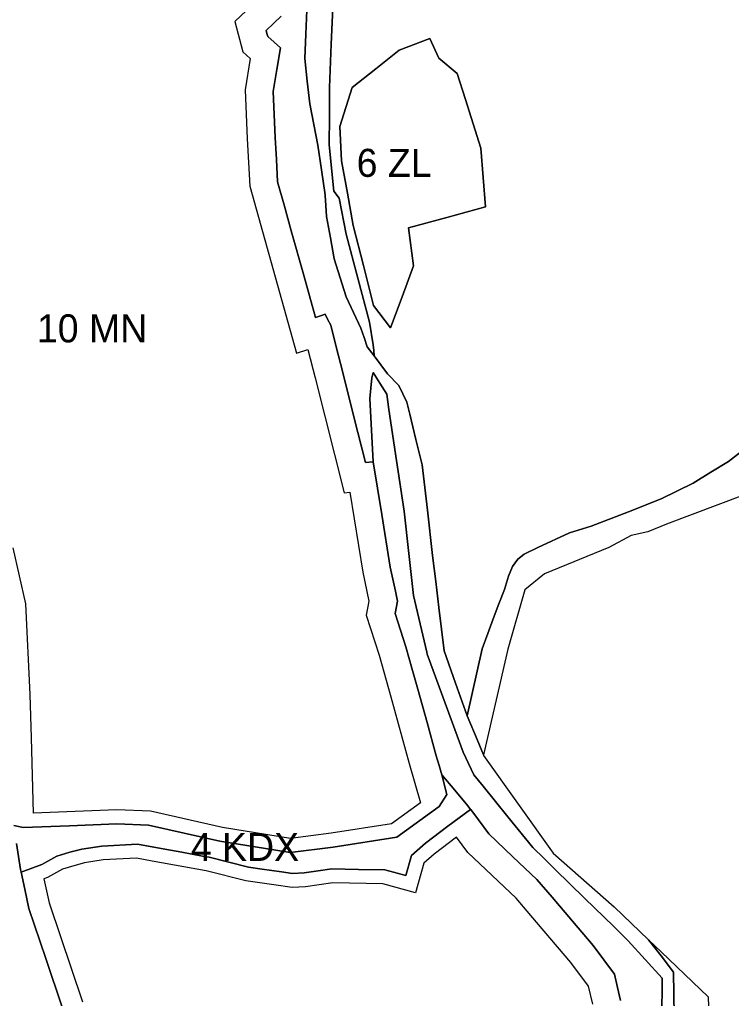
# Model space of a CAD drawing. Extents: x 7423691 to 7425475, y 5552085 to 5554331.
# Drawn here: x 7424586.6 to 7424789.8, y 5552384.7 to 5552663.9 of the extents above; entities that cross this region are included whole.
import ezdxf

# ---------------------------------------------------------------- set-up
doc = ezdxf.new("R2010")
doc.units = 0
for name, color, linetype in [('linia_zabudowy_nieprzekraczalna', 7, 'Continuous'), ('linie_rozgraniczajace', 7, 'Continuous'), ('oznaczenia_przeznaczen', 7, 'Continuous')]:
    doc.layers.add(name, color=color, linetype=linetype)

msp = doc.modelspace()

# ---------------------------------------------------------------- linework, layer by layer
at = {"layer": 'linia_zabudowy_nieprzekraczalna'}
for points in [[(7424652.99, 5552668.07), (7424648.05, 5552663.36), (7424650.33, 5552654.77), (7424652.45, 5552652.88), (7424650.97, 5552643.95), (7424651.59, 5552629.88), (7424652.3, 5552616.38), (7424665.67, 5552568.76), (7424668.93, 5552569.83), (7424671.01, 5552561.69), (7424679.28, 5552528.94), (7424680.84, 5552529.09), (7424684.57, 5552506.25), (7424686.32, 5552498.02), (7424685.51, 5552494.03), (7424689.21, 5552482.64), (7424692.6, 5552470.77), (7424697.85, 5552451.69), (7424701.04, 5552440.51), (7424692.72, 5552434.49), (7424675.54, 5552431.79), (7424663.95, 5552430.31), (7424644.53, 5552433.48), (7424623.94, 5552438.1), (7424614.37, 5552438.45), (7424590.57, 5552437.52), (7424590, 5552459.04), (7424589.67, 5552471.43), (7424588.36, 5552497.25), (7424584.74, 5552513.23)], [(7424750.2, 5552383.01), (7424748.98, 5552388.13), (7424743.98, 5552394.96), (7424732.52, 5552408.34), (7424728.3, 5552413.26), (7424714.57, 5552426.28), (7424711.31, 5552430.64), (7424704.96, 5552425.88), (7424701.98, 5552423.27), (7424699.66, 5552414.8), (7424690.27, 5552417.38), (7424676.02, 5552417.62), (7424668.26, 5552416.52), (7424664.37, 5552416.29), (7424659.2, 5552417.06), (7424651.17, 5552418.22), (7424639.85, 5552421.06), (7424624.43, 5552423.87), (7424620.02, 5552424.68), (7424610.48, 5552424.18), (7424605.15, 5552423.32), (7424602.08, 5552422.55), (7424598.84, 5552421.55), (7424594.6, 5552419.21), (7424593.57, 5552418.83), (7424595.08, 5552411.93), (7424604.56, 5552383.75)]]:
    msp.add_lwpolyline(points, dxfattribs=at)
at = {"layer": 'linie_rozgraniczajace'}
for points in [[(7424676.09, 5552669.35), (7424675.59, 5552656.96), (7424675.09, 5552644.56), (7424675.05, 5552636.4), (7424675, 5552628.25), (7424676.3, 5552615.01), (7424677.81, 5552613), (7424679.87, 5552602.69), (7424683.17, 5552590.17), (7424686.46, 5552577.65), (7424687.57, 5552571.15), (7424687.68, 5552569.56), (7424687.79, 5552567.97), (7424685.8, 5552570.62), (7424684.92, 5552573.25), (7424684.03, 5552575.88), (7424681.92, 5552580.34), (7424679.8, 5552584.8), (7424678.12, 5552590.26), (7424676.43, 5552595.72), (7424675.33, 5552601.72), (7424674.23, 5552607.73), (7424674.03, 5552610.86), (7424673.85, 5552613.72), (7424673.83, 5552613.99), (7424672.8, 5552621.07), (7424671.77, 5552628.15), (7424670.61, 5552634.05), (7424669.45, 5552639.95), (7424668.74, 5552646.42), (7424668.02, 5552652.88), (7424668.3, 5552659.76), (7424668.57, 5552666.64)], [(7424694.82, 5552559.59), (7424691.65, 5552562.83), (7424689.72, 5552565.4), (7424687.79, 5552567.97), (7424687.68, 5552569.56), (7424687.57, 5552571.15), (7424686.46, 5552577.65), (7424683.17, 5552590.17), (7424679.87, 5552602.69), (7424677.81, 5552613), (7424676.3, 5552615.01), (7424675, 5552628.25), (7424675.05, 5552636.4), (7424675.09, 5552644.56), (7424675.59, 5552656.96), (7424676.09, 5552669.35)], [(7424668.57, 5552666.64), (7424668.3, 5552659.76), (7424668.02, 5552652.88), (7424668.74, 5552646.42), (7424669.45, 5552639.95), (7424670.61, 5552634.05), (7424671.77, 5552628.15), (7424672.8, 5552621.07), (7424673.83, 5552613.99), (7424673.85, 5552613.72), (7424674.03, 5552610.86), (7424674.23, 5552607.73), (7424675.33, 5552601.72), (7424676.43, 5552595.72), (7424678.12, 5552590.26), (7424679.8, 5552584.8), (7424681.92, 5552580.34), (7424684.03, 5552575.88), (7424684.92, 5552573.25), (7424685.8, 5552570.62), (7424687.79, 5552567.97), (7424689.72, 5552565.4), (7424691.65, 5552562.83), (7424694.82, 5552559.59), (7424695.99, 5552557.18), (7424697.15, 5552554.78), (7424697.98, 5552551.37), (7424699.74, 5552544.14), (7424701.51, 5552536.91), (7424703.01, 5552523.99), (7424704.51, 5552511.07), (7424705.39, 5552503.65), (7424706.28, 5552496.22), (7424707.01, 5552490.04), (7424707.75, 5552483.85), (7424711.07, 5552474.59), (7424714.39, 5552465.34), (7424715.15, 5552463.48), (7424716.71, 5552459.73), (7424719.02, 5552454.16), (7424718.98, 5552453.98), (7424738.87, 5552426.09), (7424756.36, 5552410.77), (7424766.12, 5552401.43), (7424769.7, 5552396.82), (7424773.28, 5552392.2), (7424773.42, 5552379.79)], [(7424661.29, 5552664.94), (7424659.14, 5552662.89), (7424657, 5552660.84), (7424657.22, 5552659.99), (7424657.45, 5552659.15), (7424659.26, 5552657.53), (7424661.07, 5552655.92), (7424660.03, 5552649.7), (7424658.99, 5552643.47), (7424659.29, 5552636.87), (7424659.58, 5552630.27), (7424659.91, 5552623.98), (7424660.24, 5552617.69), (7424662.2, 5552610.71), (7424664.16, 5552603.72), (7424667.63, 5552591.35), (7424671.11, 5552578.97), (7424672.46, 5552579.42), (7424673.81, 5552579.86), (7424674.62, 5552578.31), (7424675.42, 5552576.76), (7424677.09, 5552570.21), (7424678.76, 5552563.66), (7424682.06, 5552550.61), (7424685.36, 5552537.56), (7424687.52, 5552537.76), (7424689.98, 5552522.75), (7424692.43, 5552507.73), (7424693.89, 5552500.9), (7424694.5, 5552498.06), (7424693.77, 5552494.49), (7424695.31, 5552489.73), (7424696.86, 5552484.97), (7424698.58, 5552478.95), (7424700.3, 5552472.93), (7424702.93, 5552463.39), (7424705.56, 5552453.85), (7424706.33, 5552451.14), (7424707.1, 5552448.44), (7424708.59, 5552442.85), (7424706.37, 5552439.43), (7424694.29, 5552430.69), (7424676.1, 5552427.83), (7424663.88, 5552426.27), (7424653.83, 5552427.91), (7424643.77, 5552429.55), (7424633.6, 5552431.84), (7424623.42, 5552434.12), (7424614.37, 5552434.45), (7424600.87, 5552433.92), (7424587.67, 5552433.41), (7424584.95, 5552434.02)], [(7424689.47, 5552560.17), (7424687.53, 5552563.24), (7424687.14, 5552561.78), (7424686.85, 5552558.79), (7424686.57, 5552555.8), (7424687.04, 5552546.78), (7424687.52, 5552537.76), (7424685.36, 5552537.56), (7424682.06, 5552550.61), (7424678.76, 5552563.66), (7424677.09, 5552570.21), (7424675.42, 5552576.76), (7424674.62, 5552578.31), (7424673.81, 5552579.86), (7424672.46, 5552579.42), (7424671.11, 5552578.97), (7424667.63, 5552591.35), (7424664.16, 5552603.72), (7424662.2, 5552610.71), (7424660.24, 5552617.69), (7424659.91, 5552623.98), (7424659.58, 5552630.27), (7424659.29, 5552636.87), (7424658.99, 5552643.47), (7424660.03, 5552649.7), (7424661.07, 5552655.92), (7424659.26, 5552657.53), (7424657.45, 5552659.15), (7424657.22, 5552659.99), (7424657, 5552660.84), (7424659.14, 5552662.89), (7424661.29, 5552664.94)], [(7424686.57, 5552555.8), (7424686.85, 5552558.79), (7424687.14, 5552561.78), (7424687.53, 5552563.24), (7424689.47, 5552560.17), (7424691.41, 5552557.1), (7424692.05, 5552552.73), (7424694.2, 5552538.19), (7424696.35, 5552523.65), (7424697.72, 5552511.64), (7424699.09, 5552499.62), (7424700.98, 5552491.53), (7424702.87, 5552483.44), (7424702.99, 5552482.86), (7424708.09, 5552468.9), (7424713.19, 5552454.95), (7424714.74, 5552451.72), (7424716.29, 5552448.48), (7424717.6, 5552446.86), (7424718.91, 5552445.24), (7424726, 5552436.5), (7424733.09, 5552427.75), (7424736.3, 5552424.59), (7424739.51, 5552421.43), (7424747.87, 5552413.32), (7424756.24, 5552405.22), (7424760.31, 5552401.09), (7424765.15, 5552395.77), (7424769.99, 5552390.45), (7424769.9, 5552378.7)], [(7424769.9, 5552378.7), (7424769.99, 5552390.45), (7424765.15, 5552395.77), (7424760.31, 5552401.09), (7424756.24, 5552405.22), (7424747.87, 5552413.32), (7424739.51, 5552421.43), (7424736.3, 5552424.59), (7424733.09, 5552427.75), (7424726, 5552436.5), (7424718.91, 5552445.24), (7424717.6, 5552446.86), (7424716.29, 5552448.48), (7424714.74, 5552451.72), (7424713.19, 5552454.95), (7424708.09, 5552468.9), (7424702.99, 5552482.86), (7424702.87, 5552483.44), (7424700.98, 5552491.53), (7424699.09, 5552499.62), (7424697.72, 5552511.64), (7424696.35, 5552523.65), (7424694.2, 5552538.19), (7424692.05, 5552552.73), (7424691.41, 5552557.1), (7424689.47, 5552560.17)], [(7424797.91, 5552544.77), (7424788.94, 5552537.9), (7424783.92, 5552534.8), (7424778.91, 5552531.69), (7424769.74, 5552527.22), (7424760.37, 5552523.55), (7424749.73, 5552519.37), (7424743.59, 5552517.52), (7424734.54, 5552513.36), (7424730.64, 5552511.46), (7424728.78, 5552510.02), (7424727.29, 5552507.92), (7424726.2, 5552505.18), (7424725.02, 5552501.39), (7424723.43, 5552497.22), (7424721.82, 5552492.98), (7424720.26, 5552488.76), (7424718.65, 5552484.42), (7424714.39, 5552465.34), (7424711.07, 5552474.59), (7424707.75, 5552483.85), (7424707.01, 5552490.04), (7424706.28, 5552496.22), (7424705.39, 5552503.65), (7424704.51, 5552511.07), (7424703.01, 5552523.99), (7424701.51, 5552536.91), (7424699.74, 5552544.14), (7424697.98, 5552551.37), (7424697.15, 5552554.78), (7424695.99, 5552557.18), (7424694.82, 5552559.59)], [(7424758.16, 5552384.1), (7424757.28, 5552387.83), (7424756.39, 5552391.56), (7424753.37, 5552395.68), (7424750.34, 5552399.81), (7424744.47, 5552406.68), (7424738.6, 5552413.54), (7424734.24, 5552418.63), (7424727.4, 5552425.12), (7424720.57, 5552431.62), (7424717.56, 5552435.65), (7424715.38, 5552438.55), (7424715.36, 5552438.59), (7424714.54, 5552439.67), (7424710.82, 5552444.06), (7424707.1, 5552448.44), (7424706.33, 5552451.14), (7424705.56, 5552453.85), (7424702.93, 5552463.39), (7424700.3, 5552472.93), (7424698.58, 5552478.95), (7424696.86, 5552484.97), (7424695.31, 5552489.73), (7424693.77, 5552494.49), (7424694.5, 5552498.06), (7424693.89, 5552500.9), (7424692.43, 5552507.73), (7424689.98, 5552522.75), (7424687.52, 5552537.76), (7424687.04, 5552546.78), (7424686.57, 5552555.8)], [(7424714.39, 5552465.34), (7424718.65, 5552484.42), (7424720.26, 5552488.76), (7424721.82, 5552492.98), (7424723.43, 5552497.22), (7424725.02, 5552501.39), (7424726.2, 5552505.18), (7424727.29, 5552507.92), (7424728.78, 5552510.02), (7424730.64, 5552511.46), (7424734.54, 5552513.36), (7424743.59, 5552517.52), (7424749.73, 5552519.37), (7424760.37, 5552523.55), (7424769.74, 5552527.22), (7424778.91, 5552531.69), (7424783.92, 5552534.8), (7424788.94, 5552537.9), (7424797.91, 5552544.77)], [(7424793.23, 5552528.28), (7424771.24, 5552520), (7424765.9, 5552517.79), (7424761.17, 5552516.77), (7424754.82, 5552513.35), (7424736.47, 5552505.78), (7424730.78, 5552501.26), (7424726, 5552484.37), (7424719.02, 5552454.16), (7424716.71, 5552459.73), (7424715.15, 5552463.48), (7424714.39, 5552465.34)], [(7424584.95, 5552434.02), (7424587.67, 5552433.41), (7424600.87, 5552433.92), (7424614.37, 5552434.45), (7424623.42, 5552434.12), (7424633.6, 5552431.84), (7424643.77, 5552429.55), (7424653.83, 5552427.91), (7424663.88, 5552426.27), (7424676.1, 5552427.83), (7424694.29, 5552430.69), (7424706.37, 5552439.43), (7424708.59, 5552442.85), (7424707.1, 5552448.44), (7424710.82, 5552444.06), (7424714.54, 5552439.67), (7424715.36, 5552438.59), (7424708.88, 5552433.81), (7424702.44, 5552428.99), (7424698.44, 5552425.48), (7424696.86, 5552419.72), (7424690.84, 5552421.37), (7424683.3, 5552421.5), (7424675.77, 5552421.63), (7424671.81, 5552421.07), (7424667.86, 5552420.51), (7424664.55, 5552420.31), (7424661.37, 5552420.78), (7424655.86, 5552421.59), (7424651.94, 5552422.15), (7424646.32, 5552423.56), (7424640.7, 5552424.97), (7424638.85, 5552425.31), (7424632.92, 5552426.38), (7424628.03, 5552427.28), (7424620.28, 5552428.69), (7424610.06, 5552428.16), (7424604.35, 5552427.24), (7424601, 5552426.4), (7424597.27, 5552425.25), (7424592.94, 5552422.86), (7424587.03, 5552420.69), (7424586.86, 5552421.44), (7424585.73, 5552428.86)], [(7424587.03, 5552420.69), (7424592.94, 5552422.86), (7424597.27, 5552425.25), (7424601, 5552426.4), (7424604.35, 5552427.24), (7424610.06, 5552428.16), (7424620.28, 5552428.69), (7424628.03, 5552427.28), (7424632.92, 5552426.38), (7424638.85, 5552425.31), (7424640.7, 5552424.97), (7424646.32, 5552423.56), (7424651.94, 5552422.15), (7424655.86, 5552421.59), (7424661.37, 5552420.78), (7424664.55, 5552420.31), (7424667.86, 5552420.51), (7424671.81, 5552421.07), (7424675.77, 5552421.63), (7424683.3, 5552421.5), (7424690.84, 5552421.37), (7424696.86, 5552419.72), (7424698.44, 5552425.48), (7424702.44, 5552428.99), (7424708.88, 5552433.81), (7424715.36, 5552438.59), (7424715.38, 5552438.55), (7424717.56, 5552435.65), (7424720.57, 5552431.62), (7424727.4, 5552425.12), (7424734.24, 5552418.63), (7424738.6, 5552413.54), (7424744.47, 5552406.68), (7424750.34, 5552399.81), (7424753.37, 5552395.68), (7424756.39, 5552391.56), (7424757.28, 5552387.83), (7424758.16, 5552384.1)], [(7424585.73, 5552428.86), (7424586.86, 5552421.44), (7424587.03, 5552420.69), (7424588.08, 5552415.89), (7424589.29, 5552410.33), (7424594.07, 5552396.11), (7424598.86, 5552381.89)], [(7424598.86, 5552381.89), (7424594.07, 5552396.11), (7424589.29, 5552410.33), (7424588.08, 5552415.89), (7424587.03, 5552420.69)]]:
    msp.add_lwpolyline(points, dxfattribs=at)
for points in [[(7424678.04, 5552633.47), (7424681.55, 5552644.54), (7424688.26, 5552649.87), (7424694.97, 5552655.2), (7424703.71, 5552658.58), (7424706.23, 5552652.95), (7424711.53, 5552648.56), (7424713.87, 5552641.19), (7424718.29, 5552627.28), (7424719.56, 5552610.52), (7424708.56, 5552607.51), (7424697.57, 5552604.5), (7424699.08, 5552593.7), (7424695.78, 5552584.84), (7424692.48, 5552575.98), (7424687.62, 5552582.35), (7424684.74, 5552593.75), (7424681.87, 5552605.15), (7424680.16, 5552614.41), (7424678.45, 5552623.67)], [(7424678.04, 5552633.47), (7424678.45, 5552623.67), (7424680.16, 5552614.41), (7424681.87, 5552605.15), (7424684.74, 5552593.75), (7424687.62, 5552582.35), (7424692.48, 5552575.98), (7424695.78, 5552584.84), (7424699.08, 5552593.7), (7424697.57, 5552604.5), (7424708.56, 5552607.51), (7424719.56, 5552610.52), (7424718.29, 5552627.28), (7424713.87, 5552641.19), (7424711.53, 5552648.56), (7424706.23, 5552652.95), (7424703.71, 5552658.58), (7424694.97, 5552655.2), (7424688.26, 5552649.87), (7424681.55, 5552644.54)], [(7424766.12, 5552401.43), (7424769.77, 5552397.94), (7424783.18, 5552385.11), (7424783.46, 5552376.91), (7424781.51, 5552372.14), (7424774.86, 5552364.48), (7424770.43, 5552355.08), (7424771.99, 5552361.24), (7424773.55, 5552367.39), (7424773.42, 5552379.79), (7424773.28, 5552392.2), (7424769.7, 5552396.82)]]:
    msp.add_lwpolyline(points, close=True, dxfattribs=at)

# ---------------------------------------------------------------- texts
at = {"layer": 'oznaczenia_przeznaczen'}
for s, p in [('6 ZL', (7424682.82, 5552619.07)), ('10 MN', (7424591.56, 5552571.85)), ('4 KDX', (7424635.47, 5552423.91))]:
    msp.add_text(s, height=8, dxfattribs=at).set_placement(p)

doc.saveas('drawing.dxf')
